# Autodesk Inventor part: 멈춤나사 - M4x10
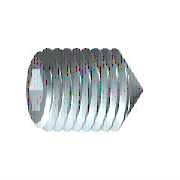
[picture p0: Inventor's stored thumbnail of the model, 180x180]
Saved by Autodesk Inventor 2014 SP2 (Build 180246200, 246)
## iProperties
Created: 2012-02
Part Number: 멈춤나사 - M4x10
Material: 강철, 연강
Description: 6각 소켓 머리 없는 멈춤 나사
Document SubType Name: Modeling
Standard: KS B 1028
Designer: mduedu
Standards Organization: KS
Language: ko-KR
Size Designation: 원추점 M4x10
Categories: <MemberInstance><Categories><Category DisplayName="조임쇠" InternalName="e4da775c-781d-43d5-af7c-5136215cf5a6" Mnemonic="FSTN"><Category DisplayName="볼트" InternalN
Density: 1 g/cm^3
Appearance: 강철
Author: mduedu
IsCustomPart: 1
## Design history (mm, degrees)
sketch "스케치1"
  geometry: L1 (0, 0)-(6.833, 0); L2 (10, 1.155)-(10, 2); L3 (10, 2)-(0, 2); L4 (10, 1.155)-(7.5, 1.155); L5 (7.5, 1.155)-(6.833, 0); L6 (0, -0.4)-(0, 2.4) reference; L7 (0, 2)-(0, 0)
  constraints: 13 end point, 3 parallel, 1 collinear, 1 perpendicular, 1 point on line
  dimensions: "d0" = 2.5 distance of L2.start L4.end (= INTI); "d1" = 60 deg angle of L5 L1; "d2" = 4 diameter of L3 L1 (= NND); "d3" = 2.3094 diameter of L4 L1 (= 1.1547 x SW); "d5" = 10 distance from line of L2 L3.end (= NLG)
revolve "본체" sketch "스케치1" stored, may be unused: angle "d6" = 90 deg
sketch "스케치2"
  geometry: L1 (-0.577, 1)-(0.577, 1); L2 (0.577, 1)-(1.155, 0); L3 (1.155, 0)-(0.577, -1); L4 (0.577, -1)-(-0.577, -1); L5 (-0.577, -1)-(-1.155, 0); L6 (-1.155, 0)-(-0.577, 1); 3 further points
  constraints: 12 end point, 1 coincident, 1 horizontal, 13 other
extrude "슬롯" join sketch "스케치2" taper "d7" = 0 deg; stored distance "d21" = 10
workaxis "Work Axis1"
workplane "Work Plane1"
body "Solid1"
feature "스레드" dims "d12" = 10 (= NLG), "d13" = 0
chamfer "모따기1" distance "d8" = 1.8 (computed from NND, SPD, FAWI); stored, may be unused: angle "d9" = 45 deg (= FAWI), second distance "d34" = 1.8 (computed from NND, SPD, FAWI)
chamfer "모따기2" distance "d10" = 0.42941 (= -0.5 x GD1 + 0.5 x NND); stored, may be unused: angle "d11" = 45 deg (= FAWI), second distance "d35" = 0.42941 (= -0.5 x GD1 + 0.5 x NND)
other parameters: "NND" = 4 [user parameter; used in 5 equation terms], "NLG" = 10 [user parameter; used in 2 equation terms], "INTI" = 2.5 [user parameter; used in 1 equation term], "FAWI" = 45 deg [user parameter; used in 4 equation terms], "SW" = 2 [user parameter; used in 2 equation terms], "GD1" = 3.14117 (= THREADDIA - 1.2269 x PTC) [user parameter; used in 2 equation terms], "d4" = 0, "FAWI1" = 45 deg [user parameter], "SPD" = 0.4 [user parameter; used in 2 equation terms], "d36" = 0, "d37" = 0, "GUL" = 0.42941 (= 0.61345 x PTC) [user parameter], "TPU" = 14.28571 (computed from PTC) [user parameter], "TOA" = 30 deg [user parameter], "THREADDIA" = 4 [user parameter; used in 1 equation term], "PTC" = 0.7 [user parameter; used in 4 equation terms], "GAL" = 0.42941 (= 0.61345 x PTC) [user parameter], "E0" = 2.31 (= 1.155 x SW) [user parameter]
